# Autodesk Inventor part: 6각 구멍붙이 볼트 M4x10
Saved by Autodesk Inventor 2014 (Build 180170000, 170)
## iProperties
Created: 2026-07
Part Number: 6각 구멍붙이 볼트 M4x10
Material: 강철, 연강
Document SubType Name: Modeling
Designer: dg
Density: 7.86 g/cm^3
Appearance: 강철
Mass: 2.0371 g
Surface Area: 3.0572 cm^2
Volume: 0.259174 cm^3
Author: jhkim
Description: 6각머리 태핑 나사
Creation Date: 2026-07-02
Sending System: Autodesk Inventor 2027
Preprocessor: ST-DEVELOPER v20.1
Author: dg
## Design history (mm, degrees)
node "6각 구멍붙이 볼트 M4x101"
body "Solid1"
node "기준1"
